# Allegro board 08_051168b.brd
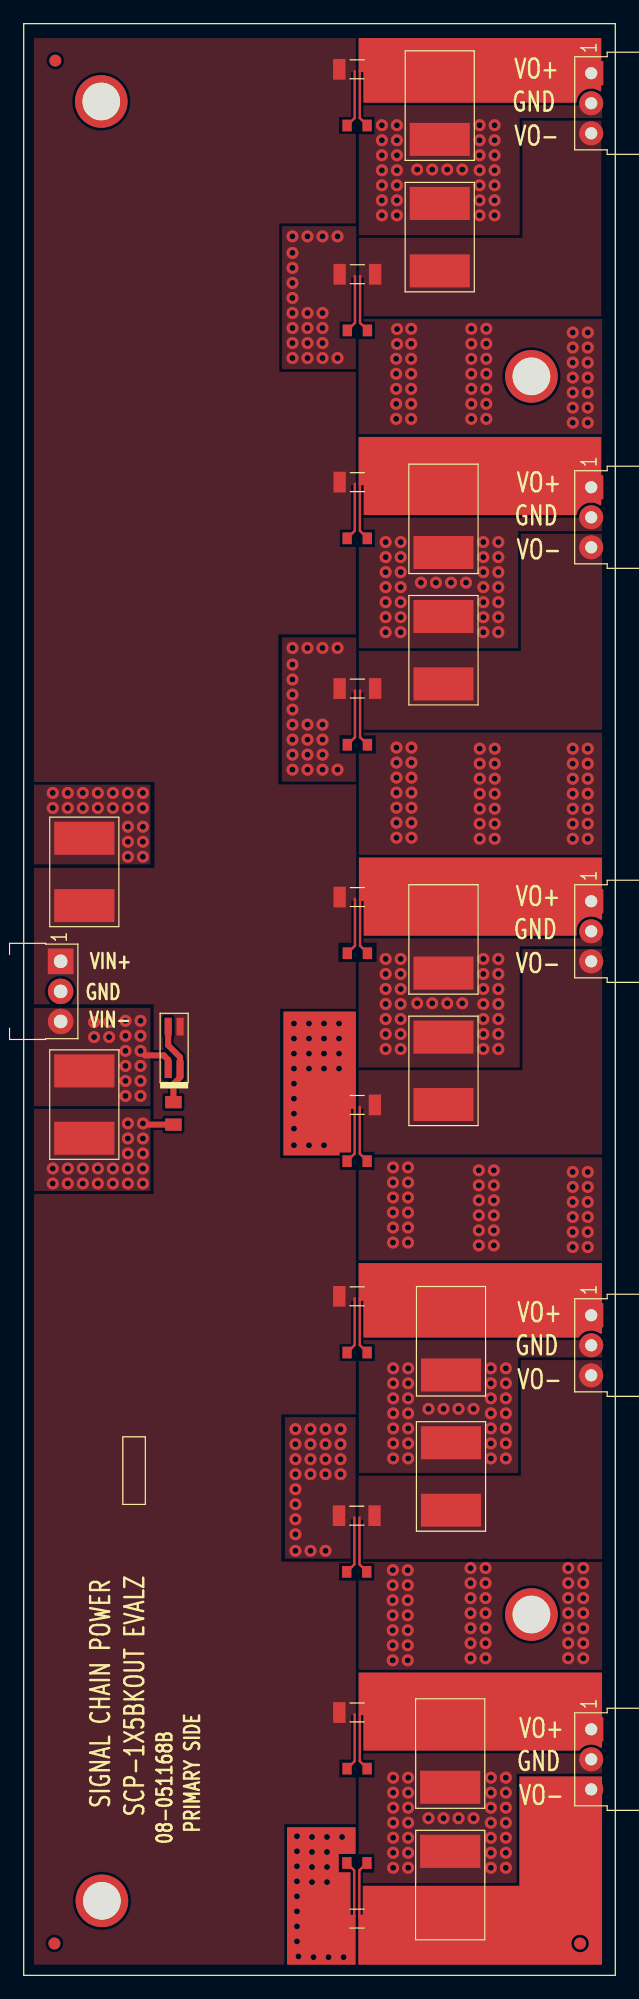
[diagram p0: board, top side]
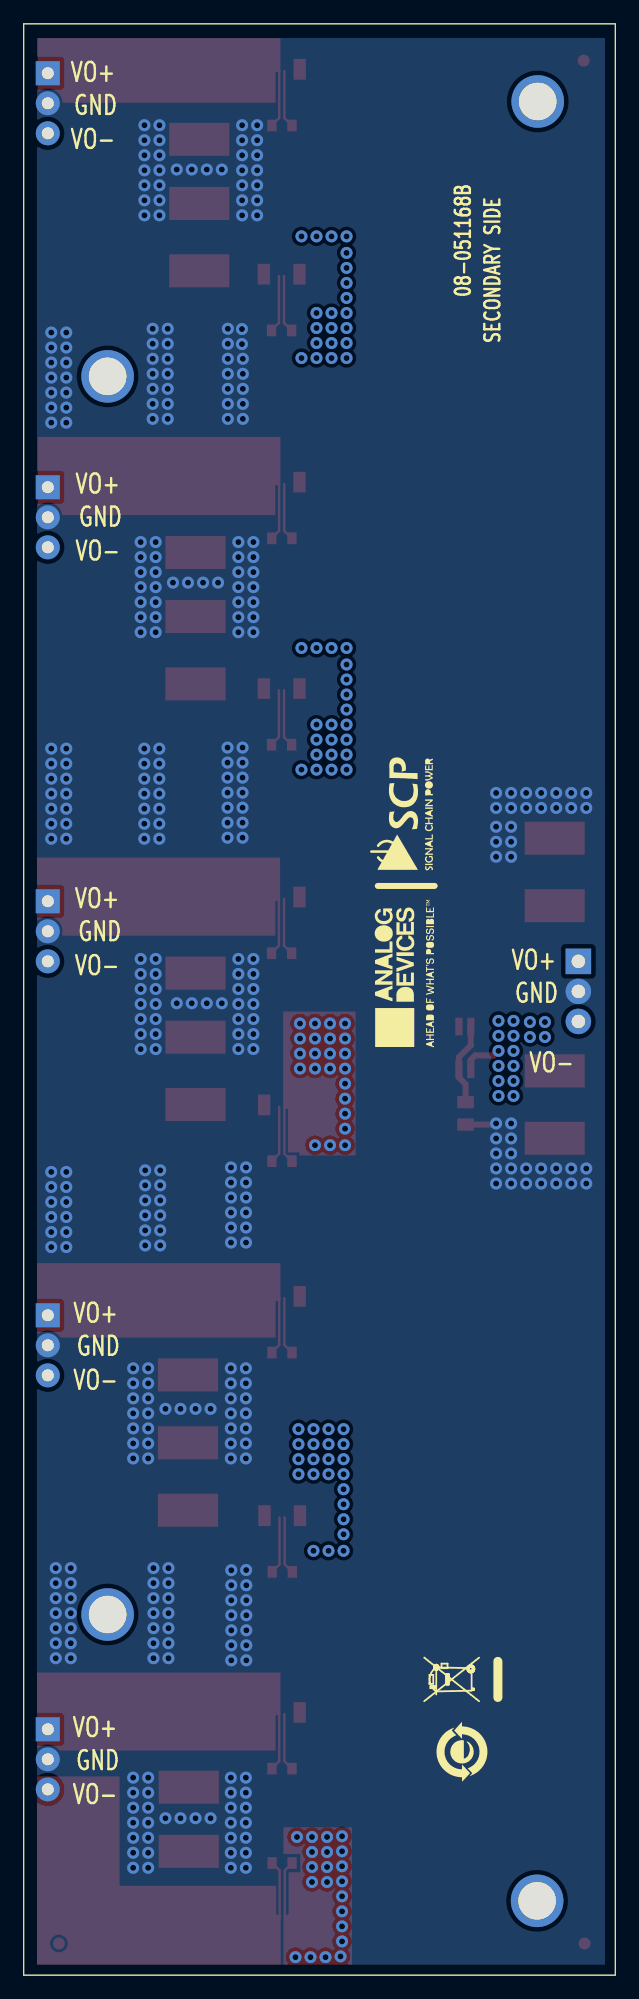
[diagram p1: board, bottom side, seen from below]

Outline 50 x 165 mm; copper layers: TOP, L2_GND, L3_GND, BOTTOM. Coordinates in mm from the lower left corner of the outline.
Outline path: 0,165 0,0 50,0 50,165 0,165

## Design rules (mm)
constraint set DEFAULT: min track width 0.203

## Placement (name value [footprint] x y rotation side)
C1  10UF  [C2220-1]  35.16 158.06 270 top
C2  10UF  [C2220-1]  35.16 146.95 270 top
C3  10UF  [C2220-1]  35.48 123.14 270 top
C4  10UF  [C2220-1]  35.48 112.03 270 top
C5  10UF  [C2220-1]  35.48 87.58 270 top
C6  10UF  [C2220-1]  35.48 76.47 270 top
C7  10UF  [C2220-1]  36.11 53.61 270 top
C8  10UF  [C2220-1]  36.11 42.18 270 top
C9  10UF  [C2220-1]  36.05 18.75 270 top
C10  10UF  [C2220-1]  36.05 7.63 270 top
C11  10UF  [C2220-1]  5.12 93.29 90 top
C12  10UF  [C2220-1]  5.12 73.62 90 top
INPUT  PBC03SBAN  [CNTHMHDRRA1X3L300W100H145]  3.12 85.72 270 top
L1  0  [R1206]  28.17 161.14 0 top
L2  0  [R1206]  28.2 143.81 0 top
L3  0  [R1206]  28.2 126.24 0 top
L4  0  [R1206]  28.2 108.79 0 top
L5  0  [R1206]  28.2 91.16 0 top
L6  0  [R1206]  28.17 73.58 0 top
L7  0  [R1206]  28.17 57.4 0 top
L8  0  [R1206]  28.15 38.86 0 top
L9  0  [R1206]  28.17 22.22 0 top
L10  0  [R1206]  28.17 4.8 0 top
LED1  LTST-C235KGKRKT  [LED1206_4P]  12.71 78.41 90 top
NOREF  -  []  50 0 0 top
NOREF#2  -  [unnamed#2]  2.6 2.69 0 top
NOREF#3  -  []  -51.37 255.79 0 top
NOREF#4  -  [unnamed#2]  2.67 161.87 0 top
NOREF#5  -  []  -172.76 -53.49 0 top
NOREF#6  -  []  -248.05 234.9 0 top
NOREF#7  -  []  50 165 0 top
NOREF#8  -  []  -137.33 279.5 0 top
NOREF#9  -  []  0 165 0 top
NOREF#10  -  []  50 0 0 top
NOREF#11  -  [unnamed#2]  42.91 30.51 0 top
NOREF#12  -  []  0 0 0 top
NOREF#13  -  []  -172 -51.33 0 top
NOREF#14  -  [unnamed#2]  47.02 2.69 0 top
NOREF#15  -  []  47.96 160.81 0 top
NOREF#16  -  []  -170.61 -51.97 0 top
NOREF#17  -  [unnamed#2]  42.91 135.18 0 top
NOREF#18  -  []  -116.1 331.09 0 top
NOREF#19  -  []  25.59 187.4 0 top
NOREF#20  -  []  0 164.97 270 top
NOREF#21  -  []  50 165 0 top
NOREF#22  -  [unnamed#2]  6.56 158.42 0 top
NOREF#23  -  []  49.99 165 180 top
NOREF#24  -  [unnamed#2]  6.61 6.3 0 top
NOREF#25  -  []  0 0 90 top
NOREF#26  -  []  50 0.03 90 top
NOREF#27  -  []  47.96 160.81 0 top
NOREF#28  -  []  0 0.02 0 top
NOREF#29  -  []  -111.58 106.27 0 top
NOREF#30  -  []  9.61 24.82 90 bottom
NOREF#31  -  []  12.96 18.9 90 bottom
NOREF#32  -  []  18.07 98.22 90 bottom
NOREF#33  -  []  17.79 84.39 90 bottom
NOREF#34  -  []  -28.21 79.04 90 bottom
NOREF#35  -  []  -27.91 92.79 90 bottom
OUTPUT1  PPPC031LGBN-RC  [CNHDRRA1X3H108]  47.96 160.81 270 top
OUTPUT2  PPPC031LGBN-RC  [CNHDRRA1X3H108]  47.96 125.81 270 top
OUTPUT3  PPPC031LGBN-RC  [CNHDRRA1X3H108]  47.96 90.81 270 top
OUTPUT4  PPPC031LGBN-RC  [CNHDRRA1X3H108]  47.96 55.8 270 top
OUTPUT5  PPPC031LGBN-RC  [CNHDRRA1X3H108]  47.96 20.8 270 top
R1  TBD0805  [R0805]  12.66 72.87 90 top
SNS1N  0  [R0603]  28.2 139.06 0 top
SNS1P  0  [R0603]  28.17 156.39 0 top
SNS2N  0  [R0603]  28.2 104.04 0 top
SNS2P  0  [R0603]  28.19 121.49 0 top
SNS3N  0  [R0603]  28.17 68.83 0 top
SNS3P  0  [R0603]  28.2 86.41 0 top
SNS4N  0  [R0603]  28.15 34.11 0 top
SNS4P  0  [R0603]  28.17 52.65 0 top
SNS5N  0  [R0603]  28.16 9.5 0 top
SNS5P  0  [R0603]  28.17 17.48 0 top

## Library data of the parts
C1-C12 = CAP: Tolerance: 10; User Part Number: UPN; alternate symbols: (); part number: CAP_SM-10UF,50V,10,E007065,C2220-1; tolerance: 10
INPUT = CN3P: Tolerance: N/A; User Part Number: UPN; alternate symbols: (CNTHMHDRRA1X3L300W100H145_SCP); part number: CN3P_TH-PBC03SBAN,E034137,CNTHMHDRRA1X3L300W100H145; tolerance: N/A
L1-L10 = RES: User Part Number: UPN; alternate symbols: (); part number: RES_SM-0,E004448,1/4W,0,R1206
LED1 = DIOLED_4P_V21: User Part Number: UPN; Tolerance: N/A; alternate symbols: (LED1206_4P_67BRDTHK); part number: DIOLED_4P_V21_SM-LTST-C235KGKRKT,2V,N/A,E034174,LED1206_4P; tolerance: N/A
OUTPUT1-OUTPUT5 = CN3P: User Part Number: UPN; Tolerance: N/A; alternate symbols: (CNHDRRA1X3H108_SCP); part number: CN3P_TH-PPPC031LGBN-RC,E034111,CNHDRRA1X3H108; tolerance: N/A
R1 = RES: User Part Number: UPN; alternate symbols: (R0805L); part number: RES_SM-TBD0805,E004051,TBD0805,TBD0805,R0805
SNS1N SNS1P SNS2N SNS2P SNS3N SNS3P SNS4N SNS4P SNS5N SNS5P = RESJMPRSHRT: User Part Number: UPN; Tolerance: N/R; alternate symbols: (); part number: RESJMPRSHRT_SM-0,E004447,N/RW,N/R,R0603; tolerance: N/R

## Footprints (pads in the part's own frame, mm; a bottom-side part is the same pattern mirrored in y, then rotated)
C2220-1
  rect 2.794x5.08 smd: 1(-2.85,0) 2(2.85,0)
CNHDRRA1X3H108
  rect 2.032x2.032 hole 1.016: 1(0,0)
  round 2.032 hole 1.016: 2(2.54,0) 3(5.08,0)
CNTHMHDRRA1X3L300W100H145
  rect 2.159x2.159 hole 1.143: 1(0,0)
  round 2.159 hole 1.143: 2(2.54,0) 3(5.08,0)
LED1206_4P
  rect 1.499x0.61 smd: 1(-1.8,-0.5) 2(1.8,-0.5) 3(1.8,0.5) 4(-1.8,0.5)
R0603
  rect 0.787x0.991 smd: 1(-0.85,0) 2(0.85,0)
R0805
  rect 1.041x1.397 smd: 1(-0.95,0) 2(0.95,0)
R1206
  rect 1.041x1.753 smd: 1(-1.5,0) 2(1.5,0)
unnamed#2
  round 1.016 smd: (0,0)

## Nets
AGND: C1.2(N2) C2.1 C3.2(N2) C4.1 C5.2(N2) C6.1 C7.2(N2) C8.1 C9.2(N2) C10.1 C11.2(N2) C12.1 INPUT.2 OUTPUT1.2 OUTPUT2.2 OUTPUT3.2 OUTPUT4.2 OUTPUT5.2 R1.1
UNNAMED_2_DIOLED4PV21_I52_A2: LED1.1 LED1.3 R1.2(N2)
V+: C11.1 INPUT.1 L1.1 L3.1 L5.1 L7.1 L9.1 LED1.2 SNS1P.1 SNS2P.1 SNS3P.1 SNS4P.1 SNS5P.1
V-: C12.2(N2) INPUT.3(N3) L2.1 L4.1 L6.1 L8.1 L10.1 LED1.4(C2) SNS1N.1 SNS2N.1 SNS3N.1 SNS4N.1 SNS5N.1
VO1+: C1.1 L1.2(N2) OUTPUT1.1 SNS1P.2(S2)
VO1-: C2.2(N2) L2.2(N2) OUTPUT1.3(N3) SNS1N.2(S2)
VO2+: C3.1 L3.2(N2) OUTPUT2.1 SNS2P.2(S2)
VO2-: C4.2(N2) L4.2(N2) OUTPUT2.3(N3) SNS2N.2(S2)
VO3+: C5.1 L5.2(N2) OUTPUT3.1 SNS3P.2(S2)
VO3-: C6.2(N2) L6.2(N2) OUTPUT3.3(N3) SNS3N.2(S2)
VO4+: C7.1 L7.2(N2) OUTPUT4.1 SNS4P.2(S2)
VO4-: C8.2(N2) L8.2(N2) OUTPUT4.3(N3) SNS4N.2(S2)
VO5+: C9.1 L9.2(N2) OUTPUT5.1 SNS5P.2(S2)
VO5-: C10.2(N2) L10.2(N2) OUTPUT5.3(N3) SNS5N.2(S2)

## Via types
v1: diameter 1.016, hole 0.508, TOP to BOTTOM, 487 vias

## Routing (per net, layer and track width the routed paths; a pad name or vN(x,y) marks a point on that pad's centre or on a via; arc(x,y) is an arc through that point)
AGND: length 2.6
  TOP w0.508: R1.1 10.18,71.92 v1(10.08,72.02)
  vias: v1(2.46,99.96) v1(2.46,98.69) v1(2.46,68.21) v1(2.46,66.94) v1(3.73,99.96) v1(3.73,98.69) v1(3.73,68.21) v1(3.73,66.94) v1(5,99.96) v1(5,98.69) v1(5,68.21) v1(5,66.94) v1(6.27,99.96) v1(6.27,98.69) v1(6.27,68.21) v1(6.27,66.94) v1(7.54,99.96) v1(7.54,98.69) v1(7.54,68.21) v1(7.54,66.94) v1(8.81,99.96) v1(8.81,98.69) v1(8.81,97.1) v1(8.81,95.83) v1(8.81,94.56) v1(8.81,72.02) v1(8.81,70.75) v1(8.81,69.48) v1(8.81,68.21) v1(8.81,66.94) v1(10.08,99.96) v1(10.08,98.69) v1(10.08,97.1) v1(10.08,95.83) v1(10.08,94.56) v1(10.08,70.75) v1(10.08,69.48) v1(10.08,68.21) v1(10.08,66.94) v1(30.27,156.41) v1(30.27,155.14) v1(30.27,153.87) v1(30.27,152.6) v1(30.27,151.33) v1(30.27,150.06) v1(30.27,148.79) v1(30.59,121.17) v1(30.59,119.9) v1(30.59,118.63) v1(30.59,117.36) v1(30.59,116.09) v1(30.59,114.82) v1(30.59,113.55) v1(30.59,85.93) v1(30.59,84.66) v1(30.59,83.39) v1(30.59,82.12) v1(30.59,80.85) v1(30.59,79.58) v1(30.59,78.31) v1(31.21,68.3) v1(31.21,67.03) v1(31.21,65.76) v1(31.21,64.49) v1(31.21,63.22) v1(31.21,61.95) v1(31.2,34.26) v1(31.18,32.98) v1(31.18,31.71) v1(31.18,30.44) v1(31.18,29.17) v1(31.18,27.9) v1(31.18,26.63) v1(31.22,51.32) v1(31.22,50.05) v1(31.22,48.78) v1(31.22,47.51) v1(31.22,46.24) v1(31.22,44.97) v1(31.22,43.7) v1(31.22,16.71) v1(31.22,15.44) v1(31.22,14.17) v1(31.22,12.9) v1(31.22,11.63) v1(31.22,10.36) v1(31.22,9.09) v1(31.48,136.66) v1(31.48,135.39) v1(31.48,134.12) v1(31.48,132.85) v1(31.48,131.58) v1(31.5,103.8) v1(31.5,102.53) v1(31.5,101.26) v1(31.5,99.99) v1(31.5,98.72) v1(31.5,97.45) v1(31.5,96.18) v1(31.54,156.41) v1(31.54,155.14) v1(31.54,153.87) v1(31.54,152.6) v1(31.54,151.33) v1(31.54,150.06) v1(31.54,148.79) v1(31.55,139.18) v1(31.55,137.91) v1(31.86,121.17) v1(31.86,119.9) v1(31.86,118.63) v1(31.86,117.36) v1(31.86,116.09) v1(31.86,114.82) v1(31.86,113.55) v1(31.86,85.93) v1(31.86,84.66) v1(31.86,83.39) v1(31.86,82.12) v1(31.86,80.85) v1(31.86,79.58) v1(31.86,78.31) v1(32.48,68.3) v1(32.48,67.03) v1(32.48,65.76) v1(32.48,64.49) v1(32.48,63.22) v1(32.48,61.95) v1(32.49,51.32) v1(32.49,50.05) v1(32.49,48.78) v1(32.49,47.51) v1(32.49,46.24) v1(32.49,44.97) v1(32.49,43.7) v1(32.45,34.25) v1(32.45,32.98) v1(32.45,31.71) v1(32.45,30.44) v1(32.45,29.17) v1(32.45,27.9) v1(32.45,26.63) v1(32.49,16.71) v1(32.49,15.44) v1(32.49,14.17) v1(32.49,12.9) v1(32.49,11.63) v1(32.49,10.36) v1(32.49,9.09) v1(32.75,139.2) v1(32.75,137.93) v1(32.75,136.66) v1(32.75,135.39) v1(32.75,134.12) v1(32.75,132.85) v1(32.75,131.58) v1(32.77,103.8) v1(32.77,102.53) v1(32.77,101.26) v1(32.77,99.99) v1(32.77,98.72) v1(32.77,97.45) v1(32.77,96.18) v1(33.25,152.67) v1(33.25,82.18) v1(33.57,117.74) v1(34.21,47.89) v1(34.21,13.28) v1(34.52,152.67) v1(34.52,82.18) v1(34.84,117.74) v1(35.48,47.89) v1(35.48,13.28) v1(35.79,152.67) v1(35.79,82.18) v1(36.11,117.74) v1(36.75,47.89) v1(36.75,13.28) v1(37.06,152.67) v1(37.06,82.18) v1(37.38,117.74) v1(37.76,34.43) v1(37.76,33.16) v1(37.76,31.89) v1(37.76,30.62) v1(37.76,29.35) v1(37.76,28.08) v1(37.76,26.81) v1(37.83,139.2) v1(37.83,137.93) v1(37.83,136.66) v1(37.83,135.39) v1(37.83,134.12) v1(37.83,132.85) v1(37.83,131.58) v1(38.02,47.89) v1(38.02,13.28) v1(38.46,68.06) v1(38.46,66.79) v1(38.46,65.52) v1(38.46,64.25) v1(38.46,62.98) v1(38.46,61.71) v1(38.53,156.41) v1(38.53,155.14) v1(38.53,153.87) v1(38.53,152.6) v1(38.53,151.33) v1(38.53,150.06) v1(38.53,148.79) v1(38.54,103.71) v1(38.54,102.44) v1(38.54,101.17) v1(38.54,99.9) v1(38.54,98.63) v1(38.54,97.36) v1(38.54,96.09) v1(38.84,121.17) v1(38.84,119.9) v1(38.84,118.63) v1(38.84,117.36) v1(38.84,116.09) v1(38.84,114.82) v1(38.84,113.55) v1(38.84,85.93) v1(38.84,84.66) v1(38.84,83.39) v1(38.84,82.12) v1(38.84,80.85) v1(38.84,79.58) v1(38.84,78.31) v1(39.1,139.2) v1(39.1,137.93) v1(39.1,136.66) v1(39.1,135.39) v1(39.1,134.12) v1(39.1,132.85) v1(39.1,131.58) v1(39.03,34.43) v1(39.03,33.16) v1(39.03,31.89) v1(39.03,30.62) v1(39.03,29.35) v1(39.03,28.08) v1(39.03,26.81) v1(39.48,51.32) v1(39.48,50.05) v1(39.48,48.78) v1(39.48,47.51) v1(39.48,46.24) v1(39.48,44.97) v1(39.48,43.7) v1(39.48,16.71) v1(39.48,15.44) v1(39.48,14.17) v1(39.48,12.9) v1(39.48,11.63) v1(39.48,10.36) v1(39.48,9.09) v1(39.8,156.41) v1(39.8,155.14) v1(39.8,153.87) v1(39.8,152.6) v1(39.8,151.33) v1(39.8,150.06) v1(39.8,148.79) v1(39.81,103.71) v1(39.81,102.44) v1(39.81,101.17) v1(39.81,99.9) v1(39.81,98.63) v1(39.81,97.36) v1(39.81,96.09) v1(39.73,68.06) v1(39.73,66.79) v1(39.73,65.52) v1(39.73,64.25) v1(39.73,62.98) v1(39.73,61.71) v1(40.11,121.17) v1(40.11,119.9) v1(40.11,118.63) v1(40.11,117.36) v1(40.11,116.09) v1(40.11,114.82) v1(40.11,113.55) v1(40.11,85.93) v1(40.11,84.66) v1(40.11,83.39) v1(40.11,82.12) v1(40.11,80.85) v1(40.11,79.58) v1(40.11,78.31) v1(40.75,51.32) v1(40.75,50.05) v1(40.75,48.78) v1(40.75,47.51) v1(40.75,46.24) v1(40.75,44.97) v1(40.75,43.7) v1(40.75,16.71) v1(40.75,15.44) v1(40.75,14.17) v1(40.75,12.9) v1(40.75,11.63) v1(40.75,10.36) v1(40.75,9.09) v1(46.02,34.43) v1(46.02,33.16) v1(46.02,31.89) v1(46.02,30.62) v1(46.02,29.35) v1(46.02,28.08) v1(46.02,26.81) v1(46.4,138.89) v1(46.4,137.62) v1(46.4,136.35) v1(46.4,135.08) v1(46.4,133.81) v1(46.4,132.54) v1(46.4,131.27) v1(46.4,103.71) v1(46.4,102.44) v1(46.4,101.17) v1(46.4,99.9) v1(46.4,98.63) v1(46.4,97.36) v1(46.4,96.09) v1(46.4,67.92) v1(46.4,66.65) v1(46.4,65.38) v1(46.4,64.11) v1(46.4,62.84) v1(46.4,61.57) v1(47.29,34.43) v1(47.29,33.16) v1(47.29,31.89) v1(47.29,30.62) v1(47.29,29.35) v1(47.29,28.08) v1(47.29,26.81) v1(47.67,138.89) v1(47.67,137.62) v1(47.67,136.35) v1(47.67,135.08) v1(47.67,133.81) v1(47.67,132.54) v1(47.67,131.27) v1(47.67,103.71) v1(47.67,102.44) v1(47.67,101.17) v1(47.67,99.9) v1(47.67,98.63) v1(47.67,97.36) v1(47.67,96.09) v1(47.67,67.92) v1(47.67,66.65) v1(47.67,65.38) v1(47.67,64.11) v1(47.67,62.84) v1(47.67,61.57)
UNNAMED_2_DIOLED4PV21_I52_A2: length 7
  TOP w0.508: R1.2 12.66,75.35 13.21,75.91 13.21,77.62 12.21,78.62 LED1.3
V+: length 24.4
  TOP w0.203: SNS5P.1 27.34,17.48 27.97,18.11 27.97,22.07 ; SNS3P.1 27.36,86.41 28,87.05 28,91.01 ; 27.98,126.09 27.98,122.12 27.35,121.49 SNS2P.1 ; 27.97,160.99 27.97,157.02 27.34,156.39 SNS1P.1 ; SNS4P.1 27.34,52.65 27.97,53.29 27.97,57.25
V-: length 27.8
  TOP w0.203: 28,108.64 28,104.67 27.36,104.04 SNS2N.1 ; SNS5N.1 27.31,9.49 27.93,8.86 27.93,4.9 ; 27.95,38.71 27.95,34.75 27.31,34.11 SNS4N.1 ; 27.97,73.43 27.97,69.47 27.34,68.83 SNS3N.1 ; SNS1N.1 27.36,139.06 28,139.7 28,143.66
  TOP w0.508: v1(9.87,78.16) 10.26,77.77 11.84,77.77 12.21,77.4 12.21,76.61
  vias: v1(5.95,80.59) v1(5.95,79.32) v1(7.22,80.59) v1(7.22,79.32) v1(8.6,80.7) v1(8.6,79.43) v1(8.6,78.16) v1(8.6,76.89) v1(8.6,75.62) v1(8.6,74.35) v1(9.87,80.7) v1(9.87,79.43) v1(9.87,76.89) v1(9.87,75.62) v1(9.87,74.35) v1(22.71,147.02) v1(22.71,145.62) v1(22.71,144.35) v1(22.71,143.08) v1(22.71,141.81) v1(22.71,140.54) v1(22.71,139.27) v1(22.71,138) v1(22.71,136.73) v1(22.71,112.22) v1(22.71,110.82) v1(22.71,109.55) v1(22.71,108.28) v1(22.71,107.01) v1(22.71,105.74) v1(22.71,104.47) v1(22.71,103.2) v1(22.71,101.93) v1(22.84,80.47) v1(22.84,79.2) v1(22.84,77.93) v1(22.84,76.66) v1(22.84,75.39) v1(22.84,74.12) v1(22.84,72.85) v1(22.84,71.58) v1(22.84,70.18) v1(22.97,46.18) v1(22.97,44.91) v1(22.97,43.64) v1(22.97,42.37) v1(22.97,41.1) v1(22.97,39.83) v1(22.97,38.56) v1(22.97,37.29) v1(22.97,35.89) v1(23.09,11.76) v1(23.09,10.49) v1(23.09,9.22) v1(23.09,7.95) v1(23.09,6.68) v1(23.09,5.41) v1(23.09,4.14) v1(23.09,2.87) v1(23.22,1.6) v1(23.98,147.02) v1(23.98,140.54) v1(23.98,139.27) v1(23.98,138) v1(23.98,136.73) v1(23.98,112.22) v1(23.98,105.74) v1(23.98,104.47) v1(23.98,103.2) v1(23.98,101.93) v1(24.11,80.47) v1(24.11,79.2) v1(24.11,77.93) v1(24.11,76.66) v1(24.11,70.18) v1(24.24,46.18) v1(24.24,44.91) v1(24.24,43.64) v1(24.24,42.37) v1(24.24,35.89) v1(24.36,11.7) v1(24.36,10.43) v1(24.36,9.16) v1(24.36,7.89) v1(24.49,1.54) v1(25.25,147.02) v1(25.25,140.54) v1(25.25,139.27) v1(25.25,138) v1(25.25,136.73) v1(25.25,112.22) v1(25.25,105.74) v1(25.25,104.47) v1(25.25,103.2) v1(25.25,101.93) v1(25.38,80.47) v1(25.38,79.2) v1(25.38,77.93) v1(25.38,76.66) v1(25.38,70.18) v1(25.51,46.18) v1(25.51,44.91) v1(25.51,43.64) v1(25.51,42.37) v1(25.51,35.89) v1(25.63,11.7) v1(25.63,10.43) v1(25.63,9.16) v1(25.63,7.89) v1(25.76,1.54) v1(26.52,147.02) v1(26.52,136.73) v1(26.52,112.22) v1(26.52,101.93) v1(26.65,80.47) v1(26.65,79.2) v1(26.65,77.93) v1(26.65,76.66) v1(26.78,46.18) v1(26.78,44.91) v1(26.78,43.64) v1(26.78,42.37) v1(26.9,11.7) v1(27.03,1.54)
VO1+: length 4.9
  TOP w0.203: 28.4,160.99 28.4,157.02 29.02,156.4 SNS1P.2
VO1-: length 4.9
  TOP w0.203: SNS1N.2 29.05,139.08 28.43,139.7 28.43,143.66
VO2+: length 4.9
  TOP w0.203: SNS2P.2 29.04,121.5 28.42,122.12 28.42,126.09
VO2-: length 4.9
  TOP w0.203: 28.43,108.64 28.43,104.67 29.05,104.05 SNS2N.2
VO3+: length 4.9
  TOP w0.203: SNS3P.2 29.05,86.42 28.43,87.05 28.43,91.01
VO3-: length 4.9
  TOP w0.203: SNS3N.2 29.02,68.85 28.4,69.47 28.4,73.43
VO4+: length 4.9
  TOP w0.203: SNS4P.2 29.02,52.67 28.4,53.29 28.4,57.25
VO4-: length 4.9
  TOP w0.203: 28.38,38.71 28.38,34.75 29,34.13 SNS4N.2
VO5+: length 4.9
  TOP w0.203: SNS5P.2 29.02,17.49 28.4,18.11 28.4,22.07
VO5-: length 4.9
  TOP w0.203: SNS5N.2 29,9.5 28.36,8.86 28.36,4.9

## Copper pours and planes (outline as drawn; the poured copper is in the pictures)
AGND on TOP: 0.87,66.31 10.73,66.31 10.73,73.25 0.87,73.25
AGND on TOP: 0.87,93.93 10.71,93.93 10.71,100.76 0.87,100.76
AGND on TOP: 28.3,163.78 48.88,163.78 48.88,0.9 28.3,0.9 28.3,8.69 29.62,8.69 29.62,10.24 28.3,10.24 28.3,16.74 29.65,16.74 29.65,18.21 28.3,18.21 28.3,33.38 29.62,33.38 29.62,34.82 28.33,34.82 28.33,51.94 29.67,51.94 29.67,53.34 28.3,53.34 28.3,68.1 29.65,68.1 29.65,69.14 28.3,69.14 28.3,85.67 29.83,85.67 29.83,87.3 28.33,87.3 28.33,103.3 29.75,103.3 29.75,104.83 28.33,104.83 28.33,120.75 29.67,120.75 29.67,122.22 28.3,122.22 28.3,138.33 29.67,138.33 29.67,139.8 28.33,139.8 28.33,140.16 28.56,140.16 28.56,143.28 28.33,143.28 28.33,155.65 29.65,155.65 29.65,157.12 28.3,157.12 ; 2 cut-outs
AGND on BOTTOM: 0.87,163.78 48.88,163.78 48.88,0.9 0.87,0.9
AGND on L2_GND: 0.87,1.09 0.87,163.02 48.75,163.02 48.75,1.09
AGND on L3_GND: 0.87,0.9 0.87,163.78 48.88,163.78 48.88,0.9
(no net) on TOP: 21.95,81.48 28.07,81.48 28.07,73.25 27.67,73.25 27.67,69.57 26.7,69.57 26.7,69.29 21.95,69.29
(no net) on TOP: 28.3,163.78 48.81,163.78 48.81,158.32 28.71,158.32 28.71,160.91 28.3,160.91
(no net) on TOP: 28.3,94.5 48.88,94.5 48.88,87.9 28.73,87.9 28.73,90.83 28.3,90.83
(no net) on TOP: 28.3,25.6 48.88,25.6 48.88,19 28.71,19 28.71,22 28.3,22
(no net) on TOP: 28.3,60.21 48.88,60.21 48.88,53.92 28.71,53.92 28.71,57.02 28.3,57.02
(no net) on TOP: 41.89,16.81 48.88,16.81 48.88,0.9 28.25,0.9 28.25,5.13 28.66,5.13 28.66,7.57 41.89,7.57
(no net) on TOP: 22.21,12.52 28.05,12.52 28.05,10.26 26.63,10.26 26.63,8.71 27.62,8.71 27.62,5.13 28.05,5.13 28.05,0.9 22.21,0.9
(no net) on TOP: 28.3,130.06 48.81,130.06 48.81,123.46 28.73,123.46 28.73,125.98 28.3,125.98
V+ on TOP: 0.87,163.78 28.07,163.78 28.07,160.91 27.67,160.91 27.67,157.1 26.65,157.1 26.65,155.68 28.07,155.68 28.07,148.11 21.6,148.11 21.6,135.56 28.07,135.56 28.07,125.98 27.67,125.98 27.67,122.22 26.73,122.22 26.73,120.75 28.07,120.75 28.07,113.36 21.52,113.36 21.52,100.69 28.1,100.69 28.1,90.83 27.69,90.83 27.69,87.3 26.6,87.3 26.6,85.67 28.07,85.67 28.07,81.71 21.67,81.71 21.67,69.09 26.7,69.09 26.7,68.1 28.07,68.1 28.07,57.02 27.67,57.02 27.67,53.37 26.7,53.37 26.7,51.94 28.07,51.94 28.07,47.42 21.77,47.42 21.77,34.98 28.07,34.98 28.07,34.85 26.65,34.85 26.65,33.38 28.07,33.38 28.07,22 27.67,22 27.67,18.24 26.68,18.24 26.68,16.74 28.07,16.74 28.07,12.78 22.03,12.78 22.03,0.9 0.87,0.9 0.87,66.07 10.98,66.07 10.98,82.09 0.87,82.09 0.87,93.62 11.06,93.62 11.06,100.89 0.87,100.89
V- on TOP (solid shape): 28.07,73.25 27.67,73.25 27.67,69.57 26.7,69.57 26.7,69.32 21.95,69.32 21.95,81.48 28.07,81.48
V- on TOP (solid shape): 28.05,10.26 26.63,10.26 26.63,8.71 27.62,8.71 27.62,5.13 28.05,5.13 28.05,0.9 22.26,0.9 22.26,12.52 28.05,12.52
V- on TOP: 0.87,73.41 0.87,81.79 10.71,81.79 10.71,73.41
V- on TOP: 26.7,104.85 26.7,103.3 28.07,103.3 28.07,100.91 21.82,100.91 21.82,113.11 28.1,113.11 28.1,108.43 27.69,108.43 27.69,104.85
V- on TOP: 27.69,139.8 26.7,139.8 26.7,138.38 28.07,138.38 28.07,135.71 21.82,135.71 21.82,147.9 28.1,147.9 28.1,143.51 27.69,143.51
V- on TOP: 22.08,47.19 28.05,47.19 28.05,38.56 27.64,38.56 27.64,35.23 22.08,35.23
V- on L3_GND: 0.87,0.9 0.87,163.78 27.79,163.78 27.79,0.9
VO1+ on TOP (solid shape): 48.81,159.39 48.76,159.3 48.65,159.3 48.32,159.46 47.96,159.51 47.12,159.18 46.72,158.36 46.72,158.32 28.71,158.32 28.71,160.91 28.3,160.91 28.3,163.78 48.81,163.78
VO1- on TOP: 42.14,156.79 48.81,156.79 48.81,140.26 28.73,140.26 28.73,143.51 28.33,143.51 28.33,146.89 42.14,146.89
VO2+ on TOP (solid shape): 48.81,124.39 48.76,124.3 48.65,124.3 48.32,124.46 47.96,124.51 47.17,124.23 46.74,123.5 46.73,123.46 28.73,123.46 28.73,125.98 28.3,125.98 28.3,130.06 48.81,130.06
VO2- on TOP: 42.02,121.87 48.88,121.87 48.88,105.3 28.73,105.3 28.73,108.43 28.33,108.43 28.33,111.96 42.02,111.96
VO3+ on TOP (solid shape): 48.88,89.34 48.82,89.25 48.71,89.26 48.36,89.45 47.96,89.51 47.08,89.15 46.72,88.27 46.72,88.14 46.74,88.02 46.72,87.93 46.64,87.9 28.73,87.9 28.73,90.83 28.33,90.83 28.33,94.5 48.88,94.5
VO3- on TOP: 42.14,86.77 48.88,86.77 48.88,69.39 29.65,69.39 29.65,69.62 28.71,69.62 28.71,73.25 28.3,73.25 28.3,76.53 42.14,76.53
VO4+ on TOP (solid shape): 48.88,54.34 48.82,54.25 48.71,54.26 48.36,54.44 47.96,54.51 47.36,54.35 46.91,53.92 28.71,53.92 28.71,57.02 28.3,57.02 28.3,60.21 48.88,60.21
VO4- on TOP: 42.02,52.02 48.88,52.02 48.88,35.18 28.68,35.18 28.68,38.51 28.3,38.51 28.3,42.24 42.02,42.24
VO5+ on TOP (solid shape): 48.88,19.34 48.82,19.25 48.71,19.26 48.36,19.44 47.96,19.51 47.4,19.37 46.96,19 28.71,19 28.71,22 28.3,22 28.3,25.6 48.88,25.6
VO5- on TOP (solid shape): 48.88,0.9 28.28,0.9 28.28,2.73 46.29,2.73 46.29,2.65 46.29,2.58 46.31,2.5 46.33,2.43 46.36,2.36 46.4,2.29 46.45,2.23 46.5,2.17 46.56,2.12 46.62,2.07 46.69,2.04 46.76,2 46.83,1.98 46.91,1.96 46.98,1.96 47.06,1.96 47.14,1.96 47.21,1.98 47.29,2 47.36,2.04 47.42,2.07 47.49,2.12 47.54,2.17 47.59,2.23 47.64,2.29 47.68,2.36 47.71,2.43 47.73,2.5 47.75,2.58 47.76,2.65 47.76,2.73 47.75,2.81 47.73,2.88 47.71,2.96 47.68,3.03 47.64,3.09 47.59,3.16 47.54,3.21 47.49,3.27 47.42,3.31 47.36,3.35 47.29,3.38 47.21,3.4 47.14,3.42 47.06,3.43 46.98,3.43 46.91,3.42 46.83,3.4 46.76,3.38 46.69,3.35 46.62,3.31 46.56,3.27 46.5,3.21 46.45,3.16 46.4,3.09 46.36,3.03 46.33,2.96 46.31,2.88 46.29,2.81 46.29,2.73 28.28,2.73 28.28,5.13 28.66,5.13 28.66,7.57 41.89,7.57 41.89,16.81 48.88,16.81

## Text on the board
Ref Des/Silkscreen Bottom: VO- | GND | VO+
User.Comments: CR_UNNAMED_5 | CR_UNNAMED_3 | CR_UNNAMED_2 | CR_UNNAMED_1 | PRIMARY SIDE
Ref Des/Silkscreen Top: GND | VIN- | VIN+ | 08-051168B | PRIMARY SIDE | VO+ | VO- | SIGNAL CHAIN POWER
PAGE_OUTLINE: 22OCT18 | B | AS PER ECR-086422 | 07MAY19 | J VIERNES
DIMENSION: (REF) | SEE FAB NOTE 15 | DIA MAX
User.15: 15.    THRU VIAS TO BE FILLED WITH SOLDEMASK.
User.17: L2 GND | 08-      -07
User.18: L3 GND | 08-      -08
User.45: FIGURE | SIZE | 20.0 | 40.0 | 45.0 | 125.0 | PLATED | NON-PLATED | FINISHED HOLES IN MILS | ALL UNITS ARE IN MILS | QTY | 487 | 15 | 3 | 4 | TOLERANCE/NOTES
